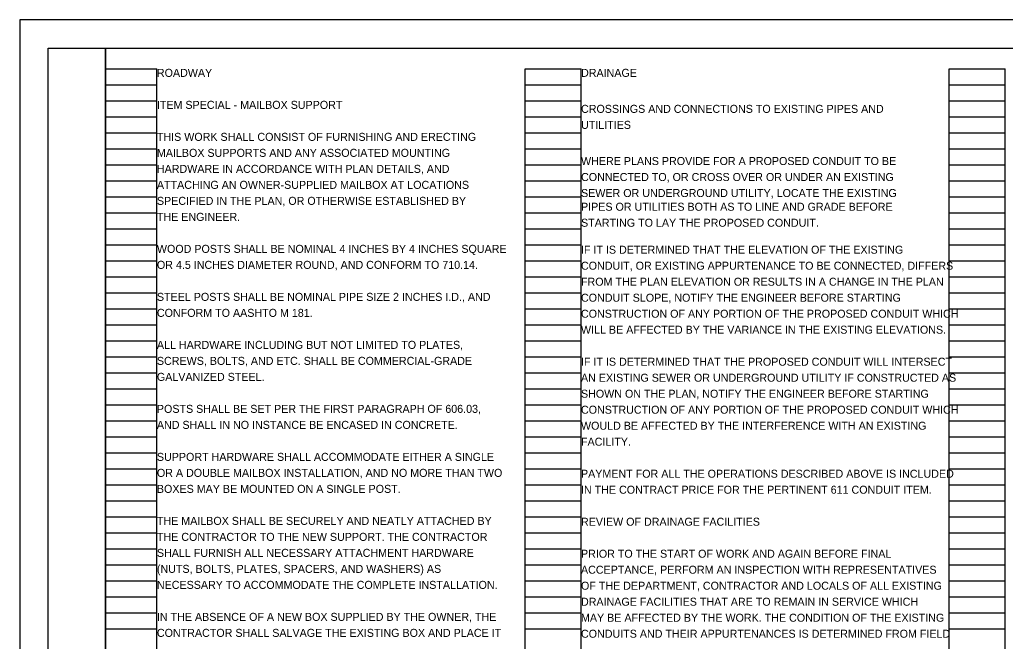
# Model space of a CAD drawing. Extents: x 0 to 34, y 0 to 22.
# Drawn here: x 0 to 17.24, y 11.12 to 22 of the extents above; entities that cross this region are included whole.
import ezdxf

# ---------------------------------------------------------------- set-up
doc = ezdxf.new("R2010")
doc.units = 0
for name, color, linetype in [('SH_Border', 7, 'Continuous'), ('SH_Cut_Line', 7, 'Continuous'), ('SH_Data', 7, 'Continuous'), ('SH_Text', 7, 'Continuous')]:
    doc.layers.add(name, color=color, linetype=linetype)

msp = doc.modelspace()

# ---------------------------------------------------------------- linework, layer by layer
at = {"layer": 'SH_Border'}
for points in [[(0.5, 21.5), (1.5, 21.5), (1.5, 0.5), (0.5, 0.5)], [(1.5, 21.5), (33.5, 21.5), (33.5, 0.5), (1.5, 0.5)]]:
    msp.add_lwpolyline(points, close=True, dxfattribs=at)
at = {"layer": 'SH_Cut_Line'}
msp.add_lwpolyline([(0, 0), (34, 0), (34, 22), (0, 22)], close=True, dxfattribs=at)
at = {"layer": 'SH_Data'}
for p, q in [((1.5, 0.98), (1.5, 21.14)), ((1.5, 21.14), (2.4, 21.14)), ((2.4, 0.98), (2.4, 21.14)), ((8.84, 0.98), (8.84, 21.14)), ((8.84, 21.14), (9.82, 21.14)), ((9.82, 0.98), (9.82, 21.14)), ((16.26, 0.98), (16.26, 21.14)), ((16.26, 21.14), (17.24, 21.14)), ((17.24, 0.98), (17.24, 21.14)), ((1.5, 20.86), (2.4, 20.86)), ((8.84, 20.86), (9.82, 20.86)), ((16.26, 20.86), (17.24, 20.86)), ((1.5, 20.58), (2.4, 20.58)), ((8.84, 20.58), (9.82, 20.58)), ((16.26, 20.58), (17.24, 20.58)), ((1.5, 20.3), (2.4, 20.3)), ((8.84, 20.3), (9.82, 20.3)), ((16.26, 20.3), (17.24, 20.3)), ((1.5, 20.02), (2.4, 20.02)), ((8.84, 20.02), (9.82, 20.02)), ((16.26, 20.02), (17.24, 20.02)), ((1.5, 19.74), (2.4, 19.74)), ((8.84, 19.74), (9.82, 19.74)), ((16.26, 19.74), (17.24, 19.74)), ((1.5, 19.46), (2.4, 19.46)), ((8.84, 19.46), (9.82, 19.46)), ((16.26, 19.46), (17.24, 19.46)), ((1.5, 19.18), (2.4, 19.18)), ((8.84, 19.18), (9.82, 19.18)), ((16.26, 19.18), (17.24, 19.18)), ((1.5, 18.9), (2.4, 18.9)), ((8.84, 18.9), (9.82, 18.9)), ((16.26, 18.9), (17.24, 18.9)), ((1.5, 18.62), (2.4, 18.62)), ((8.84, 18.62), (9.82, 18.62)), ((16.26, 18.62), (17.24, 18.62)), ((1.5, 18.34), (2.4, 18.34)), ((8.84, 18.34), (9.82, 18.34)), ((16.26, 18.34), (17.24, 18.34)), ((1.5, 18.06), (2.4, 18.06)), ((8.84, 18.06), (9.82, 18.06)), ((16.26, 18.06), (17.24, 18.06)), ((1.5, 17.78), (2.4, 17.78)), ((8.84, 17.78), (9.82, 17.78)), ((16.26, 17.78), (17.24, 17.78)), ((1.5, 17.5), (2.4, 17.5)), ((8.84, 17.5), (9.82, 17.5)), ((16.26, 17.5), (17.24, 17.5)), ((1.5, 17.22), (2.4, 17.22)), ((8.84, 17.22), (9.82, 17.22)), ((16.26, 17.22), (17.24, 17.22)), ((1.5, 16.94), (2.4, 16.94)), ((8.84, 16.94), (9.82, 16.94)), ((16.26, 16.94), (17.24, 16.94)), ((1.5, 16.66), (2.4, 16.66)), ((8.84, 16.66), (9.82, 16.66)), ((16.26, 16.66), (17.24, 16.66)), ((1.5, 16.38), (2.4, 16.38)), ((8.84, 16.38), (9.82, 16.38)), ((16.26, 16.38), (17.24, 16.38)), ((1.5, 16.1), (2.4, 16.1)), ((8.84, 16.1), (9.82, 16.1)), ((16.26, 16.1), (17.24, 16.1)), ((1.5, 15.82), (2.4, 15.82)), ((8.84, 15.82), (9.82, 15.82)), ((16.26, 15.82), (17.24, 15.82)), ((1.5, 15.54), (2.4, 15.54)), ((8.84, 15.54), (9.82, 15.54)), ((16.26, 15.54), (17.24, 15.54)), ((1.5, 15.26), (2.4, 15.26)), ((8.84, 15.26), (9.82, 15.26)), ((16.26, 15.26), (17.24, 15.26)), ((1.5, 14.98), (2.4, 14.98)), ((8.84, 14.98), (9.82, 14.98)), ((16.26, 14.98), (17.24, 14.98)), ((1.5, 14.7), (2.4, 14.7)), ((8.84, 14.7), (9.82, 14.7)), ((16.26, 14.7), (17.24, 14.7)), ((1.5, 14.42), (2.4, 14.42)), ((8.84, 14.42), (9.82, 14.42)), ((16.26, 14.42), (17.24, 14.42)), ((1.5, 14.14), (2.4, 14.14)), ((8.84, 14.14), (9.82, 14.14)), ((16.26, 14.14), (17.24, 14.14)), ((1.5, 13.86), (2.4, 13.86)), ((8.84, 13.86), (9.82, 13.86)), ((16.26, 13.86), (17.24, 13.86)), ((1.5, 13.58), (2.4, 13.58)), ((8.84, 13.58), (9.82, 13.58)), ((16.26, 13.58), (17.24, 13.58)), ((1.5, 13.3), (2.4, 13.3)), ((8.84, 13.3), (9.82, 13.3)), ((16.26, 13.3), (17.24, 13.3)), ((1.5, 13.02), (2.4, 13.02)), ((8.84, 13.02), (9.82, 13.02)), ((16.26, 13.02), (17.24, 13.02)), ((1.5, 12.74), (2.4, 12.74)), ((8.84, 12.74), (9.82, 12.74)), ((16.26, 12.74), (17.24, 12.74)), ((1.5, 12.46), (2.4, 12.46)), ((8.84, 12.46), (9.82, 12.46)), ((16.26, 12.46), (17.24, 12.46)), ((1.5, 12.18), (2.4, 12.18)), ((8.84, 12.18), (9.82, 12.18)), ((16.26, 12.18), (17.24, 12.18)), ((1.5, 11.9), (2.4, 11.9)), ((8.84, 11.9), (9.82, 11.9)), ((16.26, 11.9), (17.24, 11.9)), ((1.5, 11.62), (2.4, 11.62)), ((8.84, 11.62), (9.82, 11.62)), ((16.26, 11.62), (17.24, 11.62)), ((1.5, 11.34), (2.4, 11.34)), ((8.84, 11.34), (9.82, 11.34)), ((16.26, 11.34), (17.24, 11.34))]:
    msp.add_line(p, q, dxfattribs=at)

# ---------------------------------------------------------------- texts
at = {"layer": 'SH_Text'}
for s, p in [('ROADWAY', (2.4, 21)), ('DRAINAGE', (9.82, 21)), ('ITEM SPECIAL - MAILBOX SUPPORT', (2.4, 20.44)), ('CROSSINGS AND CONNECTIONS TO EXISTING PIPES AND', (9.82, 20.37)), ('UTILITIES', (9.82, 20.09)), ('THIS WORK SHALL CONSIST OF FURNISHING AND ERECTING', (2.4, 19.88)), ('MAILBOX SUPPORTS AND ANY ASSOCIATED MOUNTING', (2.4, 19.6)), ('WHERE PLANS PROVIDE FOR A PROPOSED CONDUIT TO BE', (9.82, 19.457)), ('HARDWARE IN ACCORDANCE WITH PLAN DETAILS, AND', (2.4, 19.32)), ('CONNECTED TO, OR CROSS OVER OR UNDER AN EXISTING', (9.82, 19.177)), ('ATTACHING AN OWNER-SUPPLIED MAILBOX AT LOCATIONS', (2.4, 19.04)), ('SEWER OR UNDERGROUND UTILITY, LOCATE THE EXISTING', (9.82, 18.897)), ('SPECIFIED IN THE PLAN, OR OTHERWISE ESTABLISHED BY', (2.4, 18.76)), ('PIPES OR UTILITIES BOTH AS TO LINE AND GRADE BEFORE', (9.82, 18.657)), ('THE ENGINEER.', (2.4, 18.48)), ('STARTING TO LAY THE PROPOSED CONDUIT.', (9.82, 18.377)), ('WOOD POSTS SHALL BE NOMINAL 4 INCHES BY 4 INCHES SQUARE', (2.4, 17.92)), ('IF IT IS DETERMINED THAT THE ELEVATION OF THE EXISTING', (9.819, 17.905)), ('OR 4.5 INCHES DIAMETER ROUND, AND CONFORM TO 710.14.', (2.4, 17.64)), ('CONDUIT, OR EXISTING APPURTENANCE TO BE CONNECTED, DIFFERS', (9.819, 17.625)), ('FROM THE PLAN ELEVATION OR RESULTS IN A CHANGE IN THE PLAN', (9.819, 17.345)), ('STEEL POSTS SHALL BE NOMINAL PIPE SIZE 2 INCHES I.D., AND', (2.4, 17.08)), ('CONDUIT SLOPE, NOTIFY THE ENGINEER BEFORE STARTING ', (9.819, 17.065)), ('CONFORM TO AASHTO M 181.', (2.4, 16.8)), ('CONSTRUCTION OF ANY PORTION OF THE PROPOSED CONDUIT WHICH ', (9.819, 16.785)), ('WILL BE AFFECTED BY THE VARIANCE IN THE EXISTING ELEVATIONS.', (9.819, 16.505)), ('ALL HARDWARE INCLUDING BUT NOT LIMITED TO PLATES,', (2.4, 16.24)), ('SCREWS, BOLTS, AND ETC. SHALL BE COMMERCIAL-GRADE', (2.4, 15.96)), ('IF IT IS DETERMINED THAT THE PROPOSED CONDUIT WILL INTERSECT ', (9.819, 15.945)), ('GALVANIZED STEEL.', (2.4, 15.68)), ('AN EXISTING SEWER OR UNDERGROUND UTILITY IF CONSTRUCTED AS ', (9.819, 15.665)), ('SHOWN ON THE PLAN, NOTIFY THE ENGINEER BEFORE STARTING ', (9.819, 15.385)), ('POSTS SHALL BE SET PER THE FIRST PARAGRAPH OF 606.03,', (2.4, 15.12)), ('CONSTRUCTION OF ANY PORTION OF THE PROPOSED CONDUIT WHICH ', (9.819, 15.105)), ('AND SHALL IN NO INSTANCE BE ENCASED IN CONCRETE.', (2.4, 14.84)), ('WOULD BE AFFECTED BY THE INTERFERENCE WITH AN EXISTING ', (9.819, 14.825)), ('FACILITY.', (9.819, 14.545)), ('SUPPORT HARDWARE SHALL ACCOMMODATE EITHER A SINGLE', (2.4, 14.28)), ('OR A DOUBLE MAILBOX INSTALLATION, AND NO MORE THAN TWO', (2.4, 14)), ('PAYMENT FOR ALL THE OPERATIONS DESCRIBED ABOVE IS INCLUDED ', (9.819, 13.985)), ('BOXES MAY BE MOUNTED ON A SINGLE POST.', (2.4, 13.72)), ('IN THE CONTRACT PRICE FOR THE PERTINENT 611 CONDUIT ITEM.', (9.819, 13.705)), ('THE MAILBOX SHALL BE SECURELY AND NEATLY ATTACHED BY', (2.4, 13.16)), ('REVIEW OF DRAINAGE FACILITIES', (9.819, 13.145)), ('THE CONTRACTOR TO THE NEW SUPPORT. THE CONTRACTOR', (2.4, 12.88)), ('SHALL FURNISH ALL NECESSARY ATTACHMENT HARDWARE', (2.4, 12.6)), ('PRIOR TO THE START OF WORK AND AGAIN BEFORE FINAL', (9.819, 12.585)), ('(NUTS, BOLTS, PLATES, SPACERS, AND WASHERS) AS', (2.4, 12.32)), ('ACCEPTANCE, PERFORM AN INSPECTION WITH REPRESENTATIVES', (9.819, 12.305)), ('NECESSARY TO ACCOMMODATE THE COMPLETE INSTALLATION.', (2.4, 12.04)), ('OF THE DEPARTMENT, CONTRACTOR AND LOCALS OF ALL EXISTING', (9.819, 12.025)), ('DRAINAGE FACILITIES THAT ARE TO REMAIN IN SERVICE WHICH', (9.819, 11.745)), ('IN THE ABSENCE OF A NEW BOX SUPPLIED BY THE OWNER, THE', (2.4, 11.48)), ('MAY BE AFFECTED BY THE WORK. THE CONDITION OF THE EXISTING', (9.819, 11.465)), ('CONTRACTOR SHALL SALVAGE THE EXISTING BOX AND PLACE IT', (2.4, 11.2)), ('CONDUITS AND THEIR APPURTENANCES IS DETERMINED FROM FIELD', (9.819, 11.185))]:
    msp.add_text(s, height=0.14, dxfattribs=at).set_placement(p)

doc.saveas('drawing.dxf')
